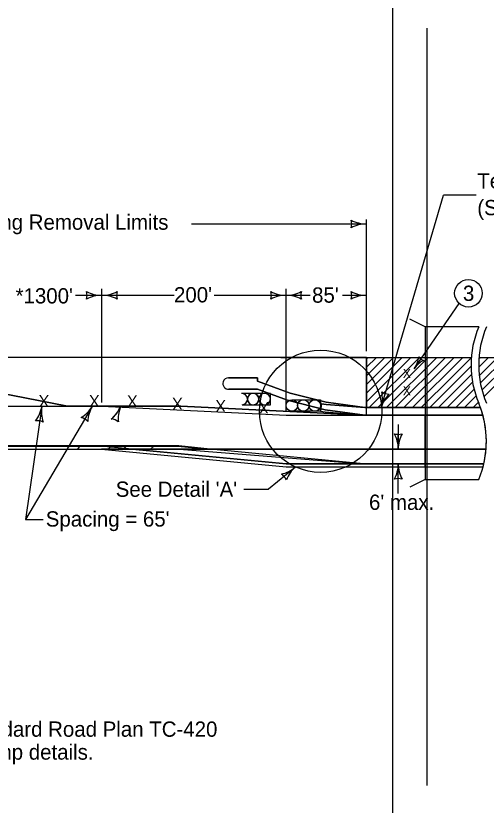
# Model space of a CAD drawing. Extents: x 10133 to 81668, y 4177 to 11018.
# Drawn here: x 26486 to 27102, y 8767 to 9800 of the extents above; entities that cross this region are included whole.
import ezdxf

# ---------------------------------------------------------------- set-up
doc = ezdxf.new("R2010")
doc.units = 0
for name, color, linetype in [('dsnNonPlotable', 7, 'Continuous'), ('dsnShtPlotShapeBatchPrint', 7, 'Continuous'), ('dsnStdDimension', 7, 'Continuous'), ('dsnStdLabel', 7, 'Continuous'), ('dsnStdLineWork', 7, 'Continuous'), ('dsnStdNote', 7, 'Continuous'), ('Level 1', 7, 'Continuous'), ('Level 2', 7, 'Continuous')]:
    doc.layers.add(name, color=color, linetype=linetype)

# ---------------------------------------------------------------- blocks, each defined once
blk = doc.blocks.new('LT')
at = {"layer": 'dsnNonPlotable'}
for centre, radius, start, end in [((-3.56, 0), 1.64, 342.2666, 17.7333), ((0, 4.25), 4.25, 241.9275, 270), ((0, -4.25), 4.25, 90, 118.0725)]:
    blk.add_arc(centre, radius, start, end, dxfattribs=at)

msp = doc.modelspace()

# ---------------------------------------------------------------- linework, layer by layer
at = {"layer": 'dsnNonPlotable'}
for p, q in [((26945.3, 9351.5), (26946.9, 9353.1)), ((26945.3, 9340.2), (26958.2, 9353.1)), ((26945.3, 9328.9), (26969.5, 9353.1)), ((26945.3, 9317.6), (26980.8, 9353.1)), ((26945.3, 9306.2), (26992.1, 9353.1)), ((26945.3, 9294.9), (27003.4, 9353.1)), ((26945.3, 9353.1), (26945.3, 9287.3)), ((26949, 9287.3), (27014.7, 9353.1)), ((26960.3, 9287.3), (27026.1, 9353.1)), ((26971.6, 9287.3), (27037.4, 9353.1)), ((26982.9, 9287.3), (27048.7, 9353.1)), ((26994.3, 9287.3), (27060, 9353.1)), ((27005.6, 9287.3), (27071.3, 9353.1)), ((27056.1, 9349.1), (27060, 9353.1)), ((27056.9, 9327.3), (27082.6, 9353.1)), ((27092.3, 9340.1), (27105.2, 9353.1)), ((27092.5, 9351.6), (27093.9, 9353.1)), ((27093, 9329.4), (27116.6, 9353.1)), ((27094.4, 9319.6), (27127.9, 9353.1)), ((27096.4, 9310.3), (27139.2, 9353.1)), ((27099, 9301.6), (27150.5, 9353.1)), ((27028.2, 9287.3), (27082.2, 9341.4)), ((27016.9, 9287.3), (27056.9, 9327.3)), ((27039.5, 9287.3), (27082.8, 9330.6)), ((27050.8, 9287.3), (27084.2, 9320.7)), ((27062.1, 9287.3), (27086.2, 9311.3)), ((27073.5, 9287.3), (27088.7, 9302.6)), ((27084.8, 9287.3), (27091.7, 9294.3)), ((26840, 9213.6), (26597.2, 9237))]:
    msp.add_line(p, q, dxfattribs=at)
for centre, radius in [((26885.2, 9282.5), 80), ((26847.7, 9290), 7.5), ((26862.7, 9290), 7.5), ((26877.7, 9290), 7.5)]:
    msp.add_circle(centre, radius, dxfattribs=at)
at = {"layer": 'dsnShtPlotShapeBatchPrint'}
for p, q in [((26979.5, 9884), (26979.5, 8414)), ((27024.5, 9784), (27024.5, 8792.5))]:
    msp.add_line(p, q, dxfattribs=at)
at = {"layer": 'dsnStdDimension'}
for p, q in [((26833.2, 9353.1), (26002.5, 9353.1)), ((26833.2, 9353.1), (27082.6, 9353.1)), ((27092.6, 9353.1), (27611.1, 9353.1)), ((26945.3, 9328.9), (26945.3, 9340.2)), ((26802.5, 9322), (26802.5, 9326.3)), ((26452.6, 9308.8), (26554.1, 9289.3)), ((26554.1, 9289.3), (26452.6, 9308.8)), ((26779.8, 9311.3), (26765.1, 9311.3)), ((26765.1, 9311.3), (26779.8, 9311.3)), ((26794.8, 9311.3), (26780.1, 9311.3)), ((26780.1, 9311.3), (26794.8, 9311.3)), ((26796.6, 9306), (26782, 9306)), ((26802.5, 9311.3), (26795.1, 9311.3)), ((26795.1, 9311.3), (26802.5, 9311.3)), ((26811.6, 9306), (26796.6, 9306)), ((26819.5, 9306), (26811.6, 9306)), ((26819.5, 9298.9), (26819.5, 9306)), ((26945.3, 9294.9), (26945.3, 9306.2)), ((26819.5, 9291), (26819.5, 9298.5)), ((26945.3, 9287.3), (26945.3, 9294.9)), ((26554.1, 9289.3), (26669.5, 9289.3)), ((26702.3, 9289.3), (26554.1, 9289.3)), ((26623.7, 9288.9), (26623.1, 9287.4)), ((26669.5, 9289.3), (26702.3, 9289.3)), ((26702.3, 9289.3), (26943.3, 9277.3)), ((26943.3, 9277.3), (26702.3, 9289.3)), ((26782.4, 9291), (26796.9, 9291)), ((26797.4, 9291), (26812.4, 9291)), ((26812.4, 9291), (26819.5, 9291)), ((26886.5, 9292.3), (26885.2, 9282.5)), ((27094.5, 9287.3), (26943.3, 9287.3)), ((26945.3, 9277.2), (26945.3, 9287.3)), ((26943.3, 9277.3), (27097.6, 9277.3)), ((27022.2, 9277.3), (26943.3, 9277.3)), ((26943.3, 9277.3), (26945.3, 9277.2)), ((27097.6, 9277.3), (27022.2, 9277.3)), ((27022.2, 9277.3), (27022.2, 9233.1)), ((27022.2, 9233.1), (27022.2, 9277.3)), ((26986.9, 9233.1), (26986.9, 9252.3)), ((26391.1, 9233.1), (26627.6, 9233.1)), ((26630.6, 9237.1), (26394.3, 9237.1)), ((26570.3, 9237.1), (26567.3, 9233.1)), ((26567.3, 9233.1), (26607.1, 9233.1)), ((26612.1, 9237.1), (26570.3, 9237.1)), ((26638.6, 9233.1), (26598.4, 9233.1)), ((26598.4, 9233.1), (26840, 9209.6)), ((26598.4, 9233.1), (26840, 9209.6)), ((26607.1, 9233.1), (26612.1, 9237.1)), ((26627.6, 9233.1), (26630.6, 9237.1)), ((26630.6, 9237.1), (26627.6, 9233.1)), ((26627.6, 9233.1), (26662.6, 9233.1)), ((26667.4, 9237.1), (26630.6, 9237.1)), ((26840, 9213.6), (26638.6, 9233.1)), ((26924.2, 9233.1), (26638.6, 9233.1)), ((26638.6, 9233.1), (26840, 9213.6)), ((26667.4, 9237.1), (26662.6, 9233.1)), ((26662.6, 9233.1), (26667.4, 9237.1)), ((26698.2, 9237), (26739.4, 9233.1)), ((26740.7, 9233.1), (26699.4, 9233.1)), ((26699.4, 9233.1), (26705.7, 9232.4)), ((26740.7, 9233.1), (26699.6, 9237.1)), ((26705.7, 9232.4), (26941.3, 9213.6)), ((26739.4, 9233.1), (26740.7, 9233.1)), ((26941.3, 9213.6), (26740.7, 9233.1)), ((26740.7, 9233.1), (26924.2, 9233.1)), ((27101.9, 9233.1), (27022.2, 9233.1)), ((27022.2, 9233.1), (27022.2, 9213.6)), ((27022.2, 9233.1), (27101.9, 9233.1)), ((27022.2, 9213.6), (27022.2, 9233.1)), ((26986.9, 9213.6), (26840, 9213.6)), ((26840, 9213.6), (26977.1, 9213.6)), ((26941.3, 9213.6), (27098.8, 9213.6)), ((26977.1, 9213.6), (26986.9, 9213.6)), ((26994.9, 9213.6), (26986.9, 9213.6)), ((26986.9, 9213.6), (26994.9, 9213.6)), ((27022.2, 9213.6), (26994.9, 9213.6)), ((26994.9, 9213.6), (27022.2, 9213.6)), ((27022.2, 9213.6), (27098.8, 9213.6)), ((27022.2, 9209.6), (27022.2, 9213.6)), ((27022.2, 9213.6), (27022.2, 9209.6)), ((27072.5, 9213.6), (27098.8, 9213.6)), ((26840, 9209.6), (27097.8, 9209.6)), ((26840, 9209.6), (26986.7, 9209.6)), ((26987.1, 9209.6), (27022.2, 9209.6)), ((27071.5, 9209.6), (27097.8, 9209.6))]:
    msp.add_line(p, q, dxfattribs=at)
for points in [[(26945.3, 9353.1), (26905, 9353.1), (26833.2, 9353.1)], [(26945.3, 9340.2), (26945.3, 9351.5), (26945.3, 9353.1)], [(26764.9, 9326.3), (26764.9, 9326.3), (26794.9, 9326.3), (26795, 9326.3), (26802.5, 9326.3)], [(26802.5, 9326.3), (26794.9, 9326.3), (26764.9, 9326.3)], [(26802.5, 9326.3), (26802.5, 9322), (26802.5, 9322)], [(26945.3, 9306.2), (26945.3, 9317.6), (26945.3, 9328.9)], [(26802.5, 9322), (26845.3, 9306.4), (26892.6, 9294.5), (26943.3, 9287.3), (26945.3, 9287.3)], [(26945.3, 9287.3), (26943.3, 9287.3), (26892.6, 9294.5), (26845.3, 9306.4), (26802.5, 9322)], [(26796.6, 9306), (26796.6, 9306)], [(26796.6, 9306), (26796.6, 9306)], [(26943.3, 9277.3), (26891.4, 9284.6), (26841.9, 9297), (26802.5, 9311.3)], [(26802.5, 9311.3), (26841.9, 9297), (26891.4, 9284.6), (26943.3, 9277.3)], [(26811.6, 9306), (26811.6, 9306)], [(26811.6, 9306), (26811.6, 9306)], [(26789.5, 9298.9), (26789.5, 9298.9)], [(26804.5, 9298.9), (26804.5, 9298.9)], [(26819.5, 9298.9), (26819.5, 9298.9)], [(26623.1, 9287.4), (26623, 9287.4)], [(26669.5, 9289.3), (26669.5, 9289.3), (26669.7, 9289.7)], [(26782.4, 9291), (26782.4, 9291)], [(26797.4, 9291), (26797.4, 9291)], [(26812.4, 9291), (26812.4, 9291)], [(26812.4, 9291), (26812.4, 9291)], [(26943.3, 9287.3), (26892.7, 9291.5), (26886.5, 9292.3)], [(26885.2, 9282.5), (26891.4, 9281.7), (26943, 9277.4), (26943.3, 9277.3)], [(26943.3, 9277.3), (26943.3, 9277.3)], [(26394.3, 9237), (26603.1, 9237), (26698.2, 9237)], [(26662.6, 9233.1), (26699.4, 9233.1), (26740.7, 9233.1)], [(26699.6, 9237.1), (26698.6, 9237.1), (26667.4, 9237.1)], [(27022.2, 9233.1), (26994.9, 9233.1), (26986.9, 9233.1), (26976.1, 9233.1), (26924.2, 9233.1)], [(26924.2, 9233.1), (26976.1, 9233.1), (26986.9, 9233.1)], [(26986.9, 9233.1), (26994.9, 9233.1), (27022.2, 9233.1)], [(27098.8, 9213.6), (27072.5, 9213.6), (27022.2, 9213.6)], [(27022.2, 9209.6), (27071.5, 9209.6), (27097.8, 9209.6)]]:
    msp.add_lwpolyline(points, dxfattribs=at)
for centre, radius, start, end in [((26764.9, 9318.8), 7.5, 90, 163.0526), ((26764.9, 9318.8), 7.5, 90, 163.0526), ((26764.9, 9318.8), 7.5, 163.0498, 270.9263), ((26764.9, 9318.8), 7.5, 163.0498, 270.9263), ((26780, 9318.8), 7.5, 268.9774, 271.0226), ((26780, 9318.8), 7.5, 268.9774, 271.0226), ((26782, 9298.5), 7.5, 3.0001, 92.9999), ((26782, 9298.5), 7.5, 2.9957, 90), ((26797, 9298.5), 7.5, 93.0448, 93), ((26797, 9298.5), 7.5, 93.0417, 177.0124), ((26795, 9318.8), 7.5, 269.0651, 270.9349), ((26795, 9318.8), 7.5, 269.0651, 270.9349), ((26797, 9298.5), 7.5, 2.9957, 92.9969), ((26812, 9298.5), 7.5, 93.006, 182.994), ((26812, 9298.5), 7.5, 92.9969, 177.0124), ((26812, 9298.5), 7.51, 3.1005, 92.8995), ((26812, 9298.5), 7.5, 2.9959, 92.9969), ((26782, 9298.5), 7.55, 273.1403, 356.6811), ((26782, 9298.5), 7.5, 273.0025, 317.9707), ((26782, 9298.5), 7.55, 317.8276, 356.6663), ((26797, 9298.5), 7.5, 183.0131, 269.6775), ((26797, 9298.5), 7.55, 273.1444, 356.677), ((26797, 9298.5), 7.5, 272.9998, 319.0541), ((26797, 9298.5), 7.55, 318.902, 356.5996), ((26812, 9298.5), 7.5, 182.9958, 273.0042), ((26812, 9298.5), 7.5, 183.0813, 273.0025), ((26812, 9298.5), 7.5, 272.9998, 3.0002), ((26812, 9298.5), 7.5, 273.0025, 0), ((26584.5, 9305.3), 42.5, 309.1847, 337.2396), ((26584.5, 9305.3), 42.5, 309.1847, 335.0317), ((26662.9, 9272.5), 42.5, 159.4861, 185.3297), ((26662.9, 9272.5), 42.5, 159.4861, 185.3297), ((26662.9, 9272.5), 42.5, 157.2572, 157.2748), ((26704.1, 9264.6), 42.5, 143.9182, 144.4611), ((26704.1, 9264.6), 42.5, 143.9006, 143.9011), ((26635.4, 9314.7), 42.5, 323.883, 323.9006), ((26972.2, 9243.1), 130, 15.2823, 19.9072), ((26972.2, 9243.1), 130, 355.5883, 15.2823), ((26609.9, 9256.1), 16.4, 49.5238, 84.9905), ((26609.9, 9256.1), 16.4, 49.5238, 84.9905), ((26986.9, 9268.7), 16.4, 252.2666, 270), ((26944.4, 9233.1), 42.5, 0.0176, 28.0725), ((27029.4, 9233.1), 42.5, 179.9824, 180), ((26972.2, 9243.1), 130, 346.8816, 355.5883), ((26944.4, 9213.6), 42.5, 354.5995, 360), ((26944.4, 9213.6), 42.5, 359.9824, 360), ((27029.4, 9213.6), 42.5, 180.0176, 185.4005), ((26972.2, 9243.1), 130, 345.0644, 346.8816)]:
    msp.add_arc(centre, radius, start, end, dxfattribs=at)
at = {"layer": 'dsnStdLabel'}
for p, q in [((27022.2, 9393.1), (27002.2, 9403.1)), ((26450.8, 9289.3), (26599, 9289.3)), ((26599, 9289.3), (26840, 9277.3)), ((26943.3, 9287.3), (27094.5, 9287.3)), ((26840, 9277.3), (26943.3, 9277.3)), ((27097.6, 9277.3), (26943.3, 9277.3)), ((24568.8, 9237), (26597.2, 9237)), ((26598.4, 9233.1), (26924.2, 9233.1)), ((26924.2, 9233.1), (27101.9, 9233.1)), ((26840, 9213.6), (27098.8, 9213.6)), ((27022.2, 9193.1), (27002.2, 9183.1))]:
    msp.add_line(p, q, dxfattribs=at)
for points in [[(27092.2, 9393.1), (27022.2, 9393.1), (27022.2, 9193.1), (27092.2, 9193.1)], [(26886.5, 9292.3), (26885.2, 9282.5), (26885.2, 9282.5)], [(26886.5, 9292.3), (26892.7, 9291.5), (26943.3, 9287.3)], [(26885.2, 9282.5), (26891.4, 9281.7), (26943.3, 9277.3)]]:
    msp.add_lwpolyline(points, dxfattribs=at)
for centre, start, end in [((27212.2, 9343.1), 157.3801, 202.6199), ((27222.2, 9343.1), 157.3801, 202.6199), ((26972.2, 9243.1), 337.3801, 22.6199)]:
    msp.add_arc(centre, 130, start, end, dxfattribs=at)
at = {"layer": 'dsnStdLineWork'}
for p, q in [((26847.7, 9297.5), (26885.2, 9297.5)), ((26885.2, 9297.5), (26885.2, 9282.5)), ((26885.2, 9282.5), (26847.7, 9282.5))]:
    msp.add_line(p, q, dxfattribs=at)
for centre in [(26847.7, 9290), (26847.7, 9290), (26862.7, 9290), (26862.7, 9290), (26877.7, 9290), (26877.7, 9290)]:
    msp.add_circle(centre, 7.5, dxfattribs=at)
at = {"layer": 'dsnStdNote'}
for p, q in [((26964.4, 9287.3), (27046.1, 9565.4)), ((27089, 9565.4), (27046.1, 9565.4)), ((26945.3, 9361.1), (26945.3, 9533.8)), ((26716.5, 9527.8), (26945.3, 9527.8)), ((26599, 9293.8), (26599, 9442.9)), ((26840, 9281.9), (26840, 9442.9)), ((26693.5, 9434.3), (26564.3, 9434.3)), ((26840, 9434.3), (26746.1, 9434.3)), ((26871.6, 9434.3), (26840, 9434.3)), ((26945.3, 9434.3), (26913.7, 9434.3)), ((27007.8, 9338.3), (27066.8, 9423.5)), ((26520.4, 9288.9), (26499.2, 9140.9)), ((26586.4, 9288.9), (26499.2, 9140.9)), ((26986.9, 9265.1), (26986.9, 9233.1)), ((26976.1, 9233.1), (26994.9, 9233.1)), ((26977.1, 9213.6), (26994.9, 9213.6)), ((26986.9, 9174.8), (26986.9, 9213.6)), ((26852.3, 9209.5), (26817, 9180.3)), ((26785, 9180.3), (26817, 9180.3)), ((26499.2, 9140.9), (26522.3, 9140.9))]:
    msp.add_line(p, q, dxfattribs=at)
for centre, radius, start, end in [((26909.7, 9527.8), 16.4, 342.2666, 17.7334), ((26945.3, 9570.3), 42.5, 241.9275, 270), ((26945.3, 9485.3), 42.5, 90, 118.0725), ((26563.3, 9434.3), 16.4, 342.2666, 17.7334), ((26599, 9476.8), 42.5, 241.9275, 270), ((26599, 9476.8), 42.5, 270, 298.0725), ((26634.6, 9434.3), 16.4, 162.2666, 197.7334), ((26804.4, 9434.3), 16.4, 342.2666, 17.7334), ((26840, 9476.8), 42.5, 241.9275, 270), ((26840, 9476.8), 42.5, 270, 298.0725), ((26875.7, 9434.3), 16.4, 162.2666, 197.7334), ((26909.7, 9434.3), 16.4, 342.2666, 17.7334), ((26945.3, 9476.8), 42.5, 241.9275, 270), ((26599, 9391.8), 42.5, 90, 118.0725), ((26599, 9391.8), 42.5, 61.9275, 90), ((26840, 9391.8), 42.5, 90, 118.0725), ((26840, 9391.8), 42.5, 61.9275, 90), ((26945.3, 9391.8), 42.5, 90, 118.0725), ((26923.6, 9299.3), 42.5, 343.6131, 11.6856), ((27005.2, 9275.3), 42.5, 135.5406, 163.6131), ((26974.4, 9321.5), 16.4, 235.8797, 271.3464), ((26478.5, 9295.8), 42.5, 322.5687, 350.6412), ((26562.3, 9282), 42.5, 170.6412, 198.7137), ((26549.7, 9310.5), 42.5, 301.4319, 329.5044), ((26623, 9267.4), 42.5, 149.5044, 177.5769), ((26568.3, 9258.2), 16.4, 41.7711, 77.2378), ((26514.6, 9253.8), 16.4, 62.9079, 98.3746), ((26986.9, 9268.7), 16.4, 252.2666, 287.7333), ((26944.4, 9233.1), 42.5, 360, 28.0725), ((27029.4, 9233.1), 42.5, 151.9275, 180), ((26944.4, 9213.6), 42.5, 331.9275, 360), ((27029.4, 9213.6), 42.5, 180, 208.0725), ((26824.4, 9241.6), 42.5, 282.974, 311.0465), ((26825.4, 9186.1), 16.4, 23.3132, 58.7799), ((26880.2, 9177.5), 42.5, 131.0465, 159.119), ((26986.9, 9177.9), 16.4, 72.2666, 107.7334)]:
    msp.add_arc(centre, radius, start, end, dxfattribs=at)
at = {"layer": 'Level 2'}
msp.add_circle((27078.7, 9437), 18, dxfattribs=at)

# ---------------------------------------------------------------- block references
at = {"layer": 'dsnStdNote', "xscale": 7.999600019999, "yscale": 7.999200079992, "rotation": -124.70293665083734}
msp.add_blockref('LT', (27007.8, 9338.3), dxfattribs=at)

# ---------------------------------------------------------------- texts
at = {"layer": 'dsnNonPlotable'}
for p in [(26992.8, 9326), (26992.8, 9303.3)]:
    msp.add_text('X', height=12, dxfattribs=at).set_placement(p)
for p in [(26529.9, 9303.8), (26595.9, 9303.8), (26645.6, 9303.6), (26704.6, 9300.2), (26761.2, 9297.4), (26817.7, 9294.6)]:
    msp.add_text('X', height=15, rotation=180, dxfattribs=at).set_placement(p)
at = {"layer": 'dsnStdNote'}
for s, p in [('Temporary Barrier Rail', (27090.3, 9574.2)), ('(See Typical 8210)', (27090.3, 9539.2)), ('Pavement Marking Removal Limits', (26272.9, 9520.2)), ("*1300'", (26486.1, 9423.7)), ("200'", (26693.4, 9425.1)), ("85'", (26874.1, 9424.7)), ("See Detail 'A'", (26617.1, 9170.5)), ("6' max.", (26948.6, 9153.4)), ("Spacing = 65'", (26525.6, 9131.5))]:
    msp.add_text(s, height=20, dxfattribs=at).set_placement(p)
at = {"layer": 'Level 1'}
for s, p in [('*See Standard Road Plan TC-420', (26347.3, 8856.3)), ('for exit ramp details.', (26347.3, 8826.3))]:
    msp.add_text(s, height=20, dxfattribs=at).set_placement(p)
at = {"layer": 'Level 2'}
msp.add_text('3', height=20, dxfattribs=at).set_placement((27071.5, 9427))

doc.saveas('drawing.dxf')
